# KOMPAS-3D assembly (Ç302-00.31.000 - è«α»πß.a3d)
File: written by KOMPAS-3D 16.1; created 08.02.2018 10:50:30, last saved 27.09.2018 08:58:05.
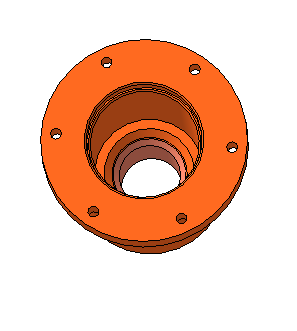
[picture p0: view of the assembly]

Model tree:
1. Эскиз:1
2. Вырезать элемент вращения:2  (labels: Полипропилен  ГОСТ 26996-86)
     Угол 1 = 360

Expressions: 20+18+2
Referenced files in Z:\Мембранные насосы\Мембранный электропривод\А302-00.00.000 - ASTRA-302 (МЭ200)\3Д\: А302-00.31.001 - Корпус.m3d
Referenced files in Z:\1 ПКИ 3D\Полипропиленовые фитинги, трубы\: Труба ф40х3,7 (PN10) FV PPR ф. FV PLAST.m3d
Referenced files: graphic.tdp
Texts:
  Труба 40 PN10 S=3,7 FV PPR ф. FV PLAST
